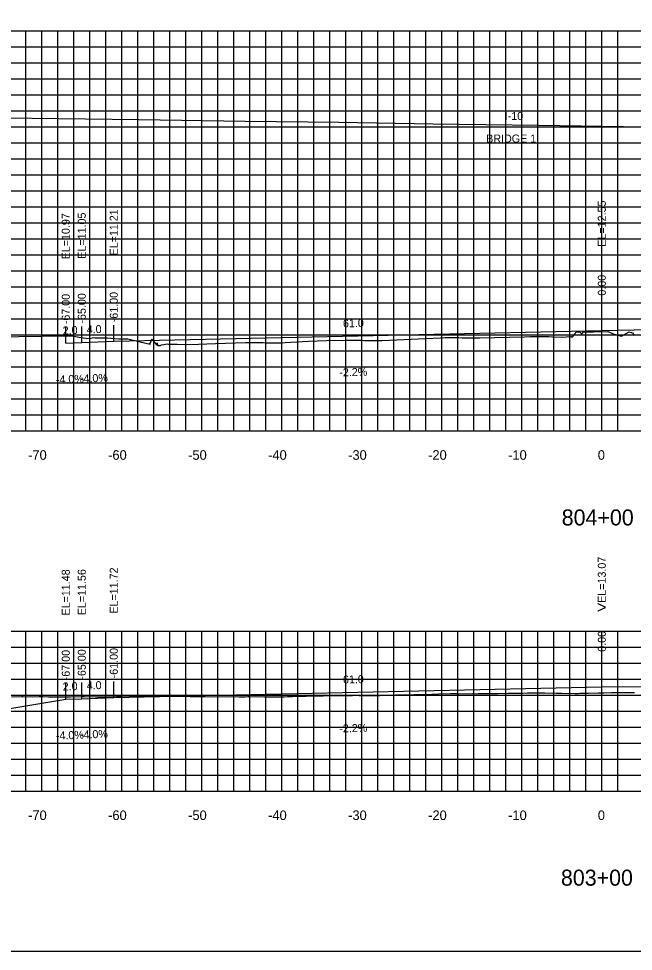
# Model space of a CAD drawing. Extents: x 1797419 to 1809236, y 248759 to 251512.
# Drawn here: x 1802898.1 to 1802974.9, y 250417.3 to 250533.8 of the extents above; entities that cross this region are included whole.
import ezdxf

# ---------------------------------------------------------------- set-up
doc = ezdxf.new("R2010")
doc.units = 0
for name, color, linetype in [('1', 7, 'Continuous'), ('10', 7, 'Continuous'), ('3', 7, 'Continuous'), ('4', 7, 'Continuous'), ('60', 7, 'Continuous'), ('CL-CNST', 7, 'Continuous'), ('Level 62', 7, 'Continuous'), ('M-ROADS', 7, 'Continuous')]:
    doc.layers.add(name, color=color, linetype=linetype)

msp = doc.modelspace()

# ---------------------------------------------------------------- linework, layer by layer
for p, q in [((1802971, 250494.81), (1802971, 250496.81)), ((1802906, 250493.31), (1802906, 250495.31)), ((1802910, 250493.47), (1802910, 250495.47)), ((1802904, 250493.23), (1802904, 250495.23)), ((1802971, 250450.32), (1802971, 250452.32)), ((1802910, 250448.98), (1802910, 250450.98)), ((1802904, 250448.74), (1802904, 250450.74)), ((1802906, 250448.82), (1802906, 250450.82))]:
    msp.add_line(p, q)
msp.add_lwpolyline([(1802821, 250417.26), (1803121, 250417.26), (1803121, 250607.26), (1802821, 250607.26)], close=True)
at = {"layer": '60'}
for p, q in [((1802821, 250482.26), (1803121, 250482.26)), ((1802901, 250482.2), (1802901, 250482.26)), ((1802911, 250482.2), (1802911, 250482.26)), ((1802921, 250482.2), (1802921, 250482.26)), ((1802931, 250482.2), (1802931, 250482.26)), ((1802941, 250482.2), (1802941, 250482.26)), ((1802951, 250482.2), (1802951, 250482.26)), ((1802961, 250482.2), (1802961, 250482.26)), ((1802971, 250482.2), (1802971, 250482.26)), ((1802821, 250437.26), (1803121, 250437.26)), ((1802901, 250437.2), (1802901, 250437.26)), ((1802911, 250437.2), (1802911, 250437.26)), ((1802921, 250437.2), (1802921, 250437.26)), ((1802931, 250437.2), (1802931, 250437.26)), ((1802941, 250437.2), (1802941, 250437.26)), ((1802951, 250437.2), (1802951, 250437.26)), ((1802961, 250437.2), (1802961, 250437.26)), ((1802971, 250437.2), (1802971, 250437.26))]:
    msp.add_line(p, q, dxfattribs=at)
at = {"layer": 'CL-CNST'}
for points in [[(1802821, 250522.15), (1802826.54, 250522.1), (1802838.13, 250522), (1802851.51, 250521.86), (1802863.13, 250521.75), (1802876.48, 250521.6), (1802888.13, 250521.47), (1802899.8, 250521.33), (1802913.13, 250521.16), (1802926.41, 250520.98), (1802938.13, 250520.82), (1802949.87, 250520.65), (1802963.13, 250520.45), (1802976.35, 250520.24)], [(1802904, 250493.23), (1802906, 250493.31), (1802910, 250493.47), (1802971, 250494.81), (1803023.67, 250495.9), (1803027.67, 250495.74), (1803029.67, 250495.66), (1803041.54, 250492.69), (1803121, 250492.69)], [(1802862.48, 250449.62), (1802880, 250445.24), (1802883, 250445.24), (1802904, 250448.74), (1802906, 250448.82), (1802910, 250448.98), (1802971, 250450.32), (1803042.76, 250450.57), (1803046.76, 250450.41), (1803048.76, 250450.33), (1803069.76, 250446.83), (1803072.76, 250446.83), (1803080.48, 250448.76)]]:
    msp.add_lwpolyline(points, dxfattribs=at)
at = {"layer": 'Level 62'}
for p, q in [((1802821, 250532.26), (1803121, 250532.26)), ((1802899, 250482.26), (1802899, 250532.26)), ((1802901, 250482.26), (1802901, 250532.26)), ((1802903, 250482.26), (1802903, 250532.26)), ((1802905, 250482.26), (1802905, 250532.26)), ((1802907, 250482.26), (1802907, 250532.26)), ((1802909, 250482.26), (1802909, 250532.26)), ((1802911, 250482.26), (1802911, 250532.26)), ((1802913, 250482.26), (1802913, 250532.26)), ((1802915, 250482.26), (1802915, 250532.26)), ((1802917, 250482.26), (1802917, 250532.26)), ((1802919, 250482.26), (1802919, 250532.26)), ((1802921, 250482.26), (1802921, 250532.26)), ((1802923, 250482.26), (1802923, 250532.26)), ((1802925, 250482.26), (1802925, 250532.26)), ((1802927, 250482.26), (1802927, 250532.26)), ((1802929, 250482.26), (1802929, 250532.26)), ((1802931, 250482.26), (1802931, 250532.26)), ((1802933, 250482.26), (1802933, 250532.26)), ((1802935, 250482.26), (1802935, 250532.26)), ((1802937, 250482.26), (1802937, 250532.26)), ((1802939, 250482.26), (1802939, 250532.26)), ((1802941, 250482.26), (1802941, 250532.26)), ((1802943, 250482.26), (1802943, 250532.26)), ((1802945, 250482.26), (1802945, 250532.26)), ((1802947, 250482.26), (1802947, 250532.26)), ((1802949, 250482.26), (1802949, 250532.26)), ((1802951, 250482.26), (1802951, 250532.26)), ((1802953, 250482.26), (1802953, 250532.26)), ((1802955, 250482.26), (1802955, 250532.26)), ((1802957, 250482.26), (1802957, 250532.26)), ((1802959, 250482.26), (1802959, 250532.26)), ((1802961, 250482.26), (1802961, 250532.26)), ((1802963, 250482.26), (1802963, 250532.26)), ((1802965, 250482.26), (1802965, 250532.26)), ((1802967, 250482.26), (1802967, 250532.26)), ((1802969, 250482.26), (1802969, 250532.26)), ((1802971, 250482.26), (1802971, 250532.26)), ((1802973, 250482.26), (1802973, 250532.26)), ((1802821, 250530.26), (1803121, 250530.26)), ((1802821, 250528.26), (1803121, 250528.26)), ((1802821, 250526.26), (1803121, 250526.26)), ((1802821, 250524.26), (1803121, 250524.26)), ((1802821, 250522.26), (1803121, 250522.26)), ((1802821, 250520.26), (1803121, 250520.26)), ((1802821, 250518.26), (1803121, 250518.26)), ((1802821, 250516.26), (1803121, 250516.26)), ((1802821, 250514.26), (1803121, 250514.26)), ((1802821, 250512.26), (1803121, 250512.26)), ((1802821, 250510.26), (1803121, 250510.26)), ((1802821, 250508.26), (1803121, 250508.26)), ((1802821, 250506.26), (1803121, 250506.26)), ((1802821, 250504.26), (1803121, 250504.26)), ((1802821, 250502.26), (1803121, 250502.26)), ((1802821, 250500.26), (1803121, 250500.26)), ((1802821, 250498.26), (1803121, 250498.26)), ((1802821, 250496.26), (1803121, 250496.26)), ((1802821, 250494.26), (1803121, 250494.26)), ((1802821, 250492.26), (1803121, 250492.26)), ((1802821, 250490.26), (1803121, 250490.26)), ((1802821, 250488.26), (1803121, 250488.26)), ((1802821, 250486.26), (1803121, 250486.26)), ((1802821, 250484.26), (1803121, 250484.26)), ((1802821, 250482.26), (1803121, 250482.26)), ((1802821, 250457.26), (1803121, 250457.26)), ((1802899, 250437.26), (1802899, 250457.26)), ((1802901, 250437.26), (1802901, 250457.26)), ((1802903, 250437.26), (1802903, 250457.26)), ((1802905, 250437.26), (1802905, 250457.26)), ((1802907, 250437.26), (1802907, 250457.26)), ((1802909, 250437.26), (1802909, 250457.26)), ((1802911, 250437.26), (1802911, 250457.26)), ((1802913, 250437.26), (1802913, 250457.26)), ((1802915, 250437.26), (1802915, 250457.26)), ((1802917, 250437.26), (1802917, 250457.26)), ((1802919, 250437.26), (1802919, 250457.26)), ((1802921, 250437.26), (1802921, 250457.26)), ((1802923, 250437.26), (1802923, 250457.26)), ((1802925, 250437.26), (1802925, 250457.26)), ((1802927, 250437.26), (1802927, 250457.26)), ((1802929, 250437.26), (1802929, 250457.26)), ((1802931, 250437.26), (1802931, 250457.26)), ((1802933, 250437.26), (1802933, 250457.26)), ((1802935, 250437.26), (1802935, 250457.26)), ((1802937, 250437.26), (1802937, 250457.26)), ((1802939, 250437.26), (1802939, 250457.26)), ((1802941, 250437.26), (1802941, 250457.26)), ((1802943, 250437.26), (1802943, 250457.26)), ((1802945, 250437.26), (1802945, 250457.26)), ((1802947, 250437.26), (1802947, 250457.26)), ((1802949, 250437.26), (1802949, 250457.26)), ((1802951, 250437.26), (1802951, 250457.26)), ((1802953, 250437.26), (1802953, 250457.26)), ((1802955, 250437.26), (1802955, 250457.26)), ((1802957, 250437.26), (1802957, 250457.26)), ((1802959, 250437.26), (1802959, 250457.26)), ((1802961, 250437.26), (1802961, 250457.26)), ((1802963, 250437.26), (1802963, 250457.26)), ((1802965, 250437.26), (1802965, 250457.26)), ((1802967, 250437.26), (1802967, 250457.26)), ((1802969, 250437.26), (1802969, 250457.26)), ((1802971, 250437.26), (1802971, 250457.26)), ((1802973, 250437.26), (1802973, 250457.26)), ((1802821, 250455.26), (1803121, 250455.26)), ((1802821, 250453.26), (1803121, 250453.26)), ((1802821, 250451.26), (1803121, 250451.26)), ((1802821, 250449.26), (1803121, 250449.26)), ((1802821, 250447.26), (1803121, 250447.26)), ((1802821, 250445.26), (1803121, 250445.26)), ((1802821, 250443.26), (1803121, 250443.26)), ((1802821, 250441.26), (1803121, 250441.26)), ((1802821, 250439.26), (1803121, 250439.26)), ((1802821, 250437.26), (1803121, 250437.26))]:
    msp.add_line(p, q, dxfattribs=at)
at = {"layer": 'M-ROADS'}
for points in [[(1802895.31, 250494.02), (1802903.71, 250494.15), (1802904.98, 250494.12), (1802906.18, 250493.91), (1802906.96, 250493.81), (1802907.46, 250493.92), (1802907.68, 250493.88), (1802908.68, 250493.88), (1802909.16, 250493.89), (1802910.62, 250493.76), (1802910.89, 250493.78), (1802910.95, 250493.74), (1802911.14, 250493.78), (1802911.56, 250493.78), (1802911.74, 250493.77), (1802914.33, 250493.13), (1802914.48, 250493.19), (1802914.54, 250493.08), (1802914.55, 250493.14), (1802914.6, 250493.35), (1802914.6, 250493.33), (1802914.64, 250493.44), (1802914.66, 250493.45), (1802914.67, 250493.54), (1802914.68, 250493.55), (1802914.7, 250493.57), (1802914.72, 250493.62), (1802914.72, 250493.64), (1802914.77, 250493.74), (1802914.77, 250493.73), (1802914.81, 250493.73), (1802914.85, 250493.62), (1802914.91, 250493.54), (1802914.94, 250493.54), (1802915.38, 250492.99), (1802915.43, 250493.28), (1802915.46, 250493.02), (1802915.48, 250492.97), (1802915.49, 250492.95), (1802915.52, 250492.96), (1802915.53, 250492.96), (1802915.63, 250492.95), (1802915.79, 250492.94), (1802915.97, 250493.02), (1802916.24, 250493.05), (1802916.67, 250493.13), (1802916.83, 250493.12), (1802917.14, 250493.12), (1802917.28, 250493.1), (1802917.94, 250493.1), (1802919.49, 250493.08), (1802922.71, 250493.18), (1802926.48, 250493.3), (1802928.37, 250493.32), (1802928.63, 250493.32), (1802928.69, 250493.32), (1802929.11, 250493.29), (1802930.89, 250493.29), (1802931.43, 250493.3), (1802932.14, 250493.34), (1802934.35, 250493.49), (1802937.7, 250493.6), (1802938.6, 250493.57), (1802939.1, 250493.59), (1802939.77, 250493.61), (1802939.99, 250493.6), (1802940.89, 250493.59), (1802941.22, 250493.57), (1802941.36, 250493.56), (1802941.43, 250493.56), (1802941.96, 250493.56), (1802943.55, 250493.58), (1802948.98, 250493.82), (1802950.82, 250493.91), (1802951.37, 250493.92), (1802953.14, 250493.92), (1802953.54, 250493.89), (1802953.62, 250493.88), (1802953.97, 250493.88), (1802955.77, 250493.91), (1802961.32, 250494.03), (1802962, 250494.05), (1802962.08, 250494.04), (1802962.23, 250494.05), (1802964.37, 250494.07), (1802964.8, 250494.02), (1802964.84, 250494.01), (1802966.12, 250494), (1802966.95, 250494.06), (1802967, 250494.05), (1802967.09, 250494), (1802967.12, 250494.04), (1802967.13, 250494.05), (1802967.15, 250494.04), (1802967.16, 250494.05), (1802967.17, 250494.04), (1802967.17, 250494.05), (1802967.17, 250494.05), (1802967.22, 250494.05), (1802967.23, 250494.02), (1802967.3, 250493.97), (1802967.42, 250494.09), (1802967.62, 250494.41), (1802967.72, 250494.48), (1802967.75, 250494.58), (1802967.75, 250494.59), (1802967.79, 250494.6), (1802967.97, 250494.63), (1802968.04, 250494.63), (1802968.22, 250494.62), (1802968.3, 250494.64), (1802968.46, 250494.32), (1802968.73, 250494.64), (1802969.95, 250494.64), (1802971.77, 250494.67), (1802972.55, 250494.37), (1802973.48, 250494.09), (1802974.41, 250494.63), (1802974.71, 250494.56), (1802974.77, 250494.51), (1802974.82, 250494.57), (1802975.06, 250494.21)], [(1802897.2, 250449.07), (1802898.49, 250449.08), (1802898.54, 250449.08), (1802898.62, 250449.08), (1802899.82, 250449.07), (1802900.69, 250449.08), (1802901.13, 250449.08), (1802901.83, 250449.07), (1802902.22, 250449.06), (1802902.69, 250449.05), (1802902.81, 250449.05), (1802902.83, 250449.05), (1802902.84, 250449.05), (1802904.58, 250449.04), (1802906.02, 250449.09), (1802906.35, 250449.09), (1802907.71, 250449.07), (1802908.16, 250449.07), (1802909.68, 250449.06), (1802910.98, 250449.14), (1802912.23, 250449.19), (1802913.43, 250449.15), (1802925.68, 250449.05), (1802926.29, 250449.05), (1802926.43, 250449.04), (1802926.77, 250449.08), (1802926.97, 250449.09), (1802928.82, 250449.05), (1802929.01, 250449.06), (1802929.43, 250449.06), (1802930.78, 250449.04), (1802931.3, 250449.04), (1802931.72, 250449.09), (1802932.34, 250449.11), (1802934.05, 250449.14), (1802938.32, 250449.22), (1802939.86, 250449.23), (1802940.43, 250449.24), (1802940.51, 250449.24), (1802940.66, 250449.23), (1802940.99, 250449.21), (1802941.16, 250449.2), (1802942.46, 250449.22), (1802943.27, 250449.23), (1802945.23, 250449.28), (1802949.77, 250449.38), (1802950.58, 250449.42), (1802952.07, 250449.47), (1802952.68, 250449.48), (1802952.87, 250449.46), (1802953.12, 250449.43), (1802954.86, 250449.45), (1802955.29, 250449.44), (1802955.53, 250449.45), (1802955.65, 250449.45), (1802955.76, 250449.45), (1802957.99, 250449.46), (1802959.27, 250449.49), (1802961.14, 250449.52), (1802961.73, 250449.53), (1802963.16, 250449.53), (1802963.62, 250449.56), (1802963.71, 250449.56), (1802963.74, 250449.57), (1802963.86, 250449.56), (1802965.3, 250449.52), (1802966, 250449.5), (1802967.65, 250449.48), (1802968.09, 250449.47), (1802968.25, 250449.49), (1802968.72, 250449.52), (1802969.01, 250449.49), (1802969.35, 250449.51), (1802970.56, 250449.56), (1802970.89, 250449.55), (1802970.98, 250449.56), (1802971.26, 250449.56), (1802972.22, 250449.58), (1802973, 250449.59), (1802973.07, 250449.59), (1802973.18, 250449.58), (1802973.67, 250449.59), (1802974.33, 250449.58), (1802975.07, 250449.59)]]:
    msp.add_lwpolyline(points, dxfattribs=at)

# ---------------------------------------------------------------- texts
at = {"layer": '1'}
for s, p in [('804+00', (1802965.99, 250470.46)), ('803+00', (1802965.89, 250425.46))]:
    msp.add_text(s, height=2, dxfattribs=at).set_placement(p)
at = {"layer": '10'}
for s, p in [('-70', (1802899.3, 250478.66)), ('-60', (1802909.3, 250478.66)), ('-50', (1802919.3, 250478.66)), ('-40', (1802929.3, 250478.66)), ('-30', (1802939.3, 250478.66)), ('-20', (1802949.3, 250478.66)), ('-10', (1802959.3, 250478.66)), ('0', (1802970.5, 250478.66)), ('-70', (1802899.3, 250433.66)), ('-60', (1802909.3, 250433.66)), ('-50', (1802919.3, 250433.66)), ('-40', (1802929.3, 250433.66)), ('-30', (1802939.3, 250433.66)), ('-20', (1802949.3, 250433.66)), ('-10', (1802959.3, 250433.66)), ('0', (1802970.5, 250433.66))]:
    msp.add_text(s, height=1.2, dxfattribs=at).set_placement(p)
at = {"layer": '3'}
for s, p in [('I-10 ', (1802958.87, 250521.11)), ('BRIDGE 1', (1802956.55, 250518.29))]:
    msp.add_text(s, height=1, dxfattribs=at).set_placement(p)
for s, p in [('EL=12.55', (1802971.5, 250505.28)), ('EL=10.97', (1802904.5, 250503.7)), ('EL=11.05', (1802906.5, 250503.78)), ('EL=11.21', (1802910.5, 250504.19)), ('0.00', (1802971.5, 250499.17)), ('-67.00', (1802904.5, 250495.6)), ('-65.00', (1802906.5, 250495.68)), ('-61.00', (1802910.5, 250495.84)), ('EL=13.07', (1802971.5, 250460.79)), ('EL=11.56', (1802906.5, 250459.24)), ('EL=11.72', (1802910.5, 250459.45)), ('EL=11.48', (1802904.5, 250459.21)), ('0.00', (1802971.5, 250454.68)), ('-67.00', (1802904.5, 250451.12)), ('-65.00', (1802906.5, 250451.2)), ('-61.00', (1802910.5, 250451.36))]:
    msp.add_text(s, height=1, rotation=90, dxfattribs=at).set_placement(p)
at = {"layer": '4'}
for s, rotation, p in [('2.0', 2.2906, (1802903.64, 250494.31)), ('4.0', 2.2906, (1802906.64, 250494.43)), ('61.0', 1.2603, (1802938.66, 250495.2)), ('-4.0%', 2.2906, (1802905.79, 250488.29)), ('-2.2%', 1.2603, (1802938.2, 250489.08)), ('-4.0%', 2.2906, (1802902.79, 250488.17)), ('4.0', 2.2906, (1802906.64, 250449.95)), ('61.0', 1.2603, (1802938.66, 250450.71)), ('2.0', 2.2906, (1802903.64, 250449.83)), ('-2.2%', 1.2603, (1802938.2, 250444.6)), ('-4.0%', 2.2906, (1802902.79, 250443.69)), ('-4.0%', 2.2906, (1802905.79, 250443.81))]:
    msp.add_text(s, height=1, rotation=rotation, dxfattribs=at).set_placement(p)
at = {"layer": '60'}
msp.add_text('>', height=1.5, dxfattribs=at).set_placement((1802970.39, 250459.51))

doc.saveas('drawing.dxf')
